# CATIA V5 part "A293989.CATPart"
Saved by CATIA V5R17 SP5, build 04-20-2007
Part number: 06F5001A1508PN-158
Revision: B
Definition: A293989
Nomenclature: BACKSHELL, 45 DEG, SHRINK BOOT ACCOM, SELF-SEATING
Source: bought
Description: BACKSHELL, 45 DEG, SHRINK BOOT ACCOM, SELF-SEATING
Publications: "Logical Termination.1", "BCP", "BCP_generated(BCP)", "Face_generated(BCP)", "BaCP", "Face_generated(BaCP)", "Line.1_generated(BaCP)"
Material "Density=.2850": density 7888.77 kg/m3
Bounding box of the stored display mesh (mm): x -7.112 to 45.125, y -15.845 to 15.845, z -26.761 to 15.845
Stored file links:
  C:\Users\u305772\OneDrive - Gulfstream Aerospace\AD PAG\Harness\A293989.CATPart
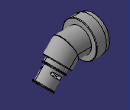
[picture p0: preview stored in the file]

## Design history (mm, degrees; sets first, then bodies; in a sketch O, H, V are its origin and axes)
Parameters
  PartNumber = "06F5001A1508PN-158"
  OtherKeywords = "BACKSHELL, 45 DEG, SHRINK BOOT ACCOM, SELF-SEATING"
  Comments = "0.866 x .039 in THREAD, ELECTROLESS NICKEL OVER STAINLESS STEEL."
  CAGECode = "07418"
  WeightComment = "SPEC"
  WeightSource = "SPEC"
  Volume = 8.93738e-06 (volume) {= smartVolume(Body1)}
  Density = 7916.45 (density)
  Weight = 0.155982 {= Volume *Density *2.20462262185}
  ExtraLength = 48.0568 mm {= C +D}
Set1
  Point1 "BCP": type Center, Curve edge [face of Shaft2 from Sketch7.L11 | face of Fillet1]
  Point2 "BaCP": type Center, Curve edge [face of Rib1 | face of Groove1 from Sketch4.L1]
  Point3: type Center, Curve edge [face of Groove1 from Sketch4.L2 | face of Slot1]
  Point4: (0, 0, 3.175), relative to Point2
  Line1: type PtPt, FirstPoint Point2, SecondPoint Point3
Body1 "PartBody" (main body)
  Sketch1 on zx-plane, origin (0, 0, 0), H (-1, 0, 0), V (0, 0, 1)
    point P1 (0, 0)
    line L1 (0, 0) -> (-18.3642, 0)
    line L2 (-18.3642, 0) -> (-26.2489, -7.8847)
    point P2 (-26.2489, -7.8847)
    point P3 (-18.3642, 0)
    point P4 (-39.36, -20.9958)
    angle L2 L1 = 45
    length L1 = 18.3642
    distance P3 P4 = 29.6926 {= D}
    distance P4 P2 = 18.542
    coincidence: P1 H, P1 V, P4 L2
    horizontal: L1 H
  Sketch2 on yz-plane, origin (0, 0, 0), H (0, 1, 0), V (0, 0, 1)
    circle A1 centre (0, 0) radius 10.9982
    construction line L1 (-10.9982, 0) -> (10.9982, 0)
    point P1 (-10.9982, 0)
    point P2 (10.9982, 0)
    length L1 = 21.9964
    coincidence: P1 A1, P1 H, A1 P2
    horizontal: L1 H
  Rib1: profile Sketch2, centre curve Sketch1
  Sketch3 on zx-plane, origin (0, 0, 0), H (-1, 0, 0), V (0, 0, 1)
    point P1 (-5.588, 11.0236)
    line L1 (-5.588, 11.0236) -> (-5.588, 15.9766)
    point P2 (-5.588, 15.9766)
    line L2 (-5.588, 15.9766) -> (3.4237, 15.9766)
    point P3 (3.4237, 15.9766)
    line L3 (3.4237, 15.9766) -> (3.937, 15.0876)
    point P4 (3.937, 15.0876)
    line L4 (3.937, 15.0876) -> (7.112, 15.0876)
    point P5 (7.112, 15.0876)
    line L5 (7.112, 15.0876) -> (7.112, 11.0236)
    point P6 (7.112, 11.0236)
    line L6 (7.112, 11.0236) -> (-5.588, 11.0236)
    axis line L7 (0, 0) -> (-5.588, 0)
    point P7 (-5.588, 0)
    point P8 (-5.588, -15.9766)
    point P9 (-5.588, -11.0236)
    construction line L8 (-5.588, -11.0236) -> (-5.588, -15.9766)
    point P10 (3.4237, -15.9766)
    construction line L9 (-5.588, -15.9766) -> (3.4237, -15.9766)
    point P11 (3.937, -15.0876)
    construction line L10 (3.4237, -15.9766) -> (3.937, -15.0876)
    point P12 (7.112, -15.0876)
    construction line L11 (3.937, -15.0876) -> (7.112, -15.0876)
    point P13 (7.112, -11.0236)
    construction line L12 (7.112, -15.0876) -> (7.112, -11.0236)
    construction line L13 (7.112, -11.0236) -> (-5.588, -11.0236)
    distance L5 L1 = 12.7
    length L4 = 3.175
    angle L4 L3 = 60
    distance L5 V = 7.112
    distance L6 L13 = 22.0472 {= `A THD` +.002 in}
    distance P5 P12 = 30.1752
    distance L4 L2 = 0.889
    vertical: L1 V, L5 V
    horizontal: L2 H, L4 H, L6 H, L7 H
    coincidence: P7 L1
    symmetry: P2 P8 L7, P1 P9 L7, L1 L8 L7, P3 P10 L7, L2 L9 L7, P4 P11 L7, L3 L10 L7, P5 P12 L7, L4 L11 L7, P6 P13 L7, L5 L12 L7, L6 L13 L7
  Shaft1: profile Sketch3, axis Sketch3.L7, angle 360
  Sketch4 on zx-plane, origin (0, 0, 0), H (-1, 0, 0), V (0, 0, 1)
    point P1 (0, 10.3632)
    line L1 (0, 10.3632) -> (-7.112, 10.3632)
    point P2 (-7.112, 10.3632)
    line L2 (-7.112, 10.3632) -> (-8.001, 9.4742)
    point P3 (-8.001, 9.4742)
    line L3 (-8.001, 9.4742) -> (-8.001, 0)
    point P4 (-8.001, 0)
    axis line L4 (-8.001, 0) -> (0, 0)
    line L5 (0, 0) -> (0, 10.3632)
    line L6 (0, 0) -> (-8.001, 0)
    point P5 (0, 0)
    point P6 (-8.001, 0)
    point P7 (-8.001, 0)
    point P8 (-8.001, -9.4742)
    construction line L7 (-8.001, -9.4742) -> (-8.001, 0)
    point P9 (-7.112, -10.3632)
    construction line L8 (-7.112, -10.3632) -> (-8.001, -9.4742)
    point P10 (0, -10.3632)
    construction line L9 (0, -10.3632) -> (-7.112, -10.3632)
    point P11 (0, 0)
    construction line L10 (0, 0) -> (0, -10.3632)
    construction line L11 (0, 0) -> (-8.001, 0)
    angle L1 L2 = 45
    length L1 = 7.112
    length L6 = 8.001
    distance L1 L9 = 20.7264 {= `A THD` -.05in}
    distance P8 P3 = 18.9484 (reference)
    coincidence: P1 V, P4 H, O L5, P4 L3, L6 L11
    horizontal: L1 H, L4 H, L6 H
    vertical: L3 V, L5 V
    symmetry: P6 P7 L4, P3 P8 L4, L3 L7 L4, P2 P9 L4, L2 L8 L4, P1 P10 L4, L1 L9 L4, P5 P11 L4, L5 L10 L4, L6 L11 L4
  Groove1: profile Sketch4, axis Sketch4.L4, angle 360
  Sketch5 on face of Groove1 from Sketch4.L3, origin (8.001, 0, 0), H (0, -1, 0), V (0, 0, 1)
    circle A1 centre (0, 0) radius 9.4742
    reference projected circle E1 centre (0, 0) radius 9.4742 from edge [face of Groove1 from Sketch4.L3 | face of Groove1 from Sketch4.L2]
    tangency: E1 A1
  Sketch6 on zx-plane, origin (0, 0, 0), H (-1, 0, 0), V (0, 0, 1)
    point P1 (-8.001, 0)
    line L1 (-8.001, 0) -> (-18.3642, 0)
    line L2 (-18.3642, 0) -> (-26.2489, -7.8847)
    point P3 (-26.2489, -7.8847)
    reference projected line E1 through (-9.1821, 9.1821) direction (-0.7071, -0.7071) from axis of face of Rib1
    reference projected line E2 (-20.5969, -13.5366) -> (-29.0814, -5.0521) from edge [face of Rib1 | face of Rib1]
    reference intersected line E3 (-8.001, -4.4755) -> (-8.001, 4.4755) from face of Groove1 from Sketch4.L3
    coincidence: P1 H, L2 E1, P3 E2, P1 E3
    horizontal: L1 H
  Slot1: profile Sketch5, centre curve Sketch6
  Sketch7 on zx-plane, origin (0, 0, 0), H (-1, 0, 0), V (0, 0, 1)
    axis line L1 (-18.3642, 0) -> (-39.36, -20.9958)
    point P1 (-18.3642, 0)
    point P2 (-39.36, -20.9958)
    point P3 (-34.8699, -25.486)
    line L2 (-34.8699, -25.486) -> (-20.8607, -11.4768)
    point P4 (-20.8607, -11.4768)
    line L3 (-20.8607, -11.4768) -> (-18.6516, -13.6859)
    line L4 (-20.2186, -13.9149) -> (-22.6433, -16.3396)
    line L5 (-22.6433, -16.3396) -> (-21.9653, -17.0176)
    point P5 (-21.9653, -17.0176)
    line L6 (-21.9653, -17.0176) -> (-22.8633, -17.9156)
    point P6 (-22.8633, -17.9156)
    line L7 (-22.8633, -17.9156) -> (-24.2193, -16.5596)
    point P7 (-24.2193, -16.5596)
    line L8 (-24.2193, -16.5596) -> (-33.1098, -25.45)
    point P8 (-33.1098, -25.45)
    line L9 (-33.1098, -25.45) -> (-32.4318, -26.1281)
    point P9 (-32.4318, -26.1281)
    line L10 (-32.4318, -26.1281) -> (-33.3298, -27.0261)
    point P10 (-33.3298, -27.0261)
    line L11 (-33.3298, -27.0261) -> (-34.8699, -25.486)
    point P11 (-29.841, -2.4965)
    point P13 (-35.3818, -3.6011)
    point P14 (-36.2798, -4.4991)
    point P15 (-34.9238, -5.8551)
    construction line L12 (-29.841, -2.4965) -> (-31.3811, -0.9564)
    construction line L13 (-31.3811, -0.9564) -> (-34.7038, -4.2791)
    construction line L14 (-34.7038, -4.2791) -> (-35.3818, -3.6011)
    construction line L15 (-35.3818, -3.6011) -> (-36.2798, -4.4991)
    construction line L16 (-36.2798, -4.4991) -> (-34.9238, -5.8551)
    point P16 (-43.8502, -16.5057)
    construction line L17 (-43.8502, -16.5057) -> (-29.841, -2.4965)
    point P17 (-43.8142, -14.7456)
    construction line L18 (-34.9238, -5.8551) -> (-43.8142, -14.7456)
    point P18 (-44.4923, -14.0676)
    construction line L19 (-43.8142, -14.7456) -> (-44.4923, -14.0676)
    point P19 (-45.3903, -14.9656)
    construction line L20 (-44.4923, -14.0676) -> (-45.3903, -14.9656)
    construction line L21 (-45.3903, -14.9656) -> (-43.8502, -16.5057)
    reference projected line E1 through (-9.1821, 9.1821) direction (-0.7071, -0.7071) from axis of face of Rib1
    reference projected line E2 (-20.5969, -13.5366) -> (-29.0814, -5.0521) from edge [face of Rib1 | face of Rib1]
    reference projected line E3 (-20.5969, -13.5366) -> (-29.0814, -5.0521) from edge [face of Rib1 | face of Rib1]
    line L22 (-20.2186, -13.9149) -> (-19.5496, -14.5839)
    point P23 (-19.5496, -14.5839)
    line L23 (-19.5496, -14.5839) -> (-18.6516, -13.6859)
    point P24 (-18.6516, -13.6859)
    point P25 (-32.0501, -0.2874)
    point P26 (-32.9481, -1.1854)
    construction line L24 (-32.9481, -1.1854) -> (-32.0501, -0.2874)
    reference intersected line E4 (-20.5969, -13.5366) -> (-29.0814, -5.0521) from face of Rib1
    length L1 = 29.6926
    length L10 = 1.27
    length L6 = 1.27
    distance L2 L17 = 12.7
    distance L8 L18 = 15.1384
    distance L6 L15 = 18.9738
    distance E2 L5 = 3.429
    distance L3 E3 = 1.27
    distance L24 L23 = 18.9484 {= Sketch4.distance(P8 P3)}
    coincidence: H P1, L11 P2, E1 L1, L22 E4
    perpendicularity: L3 L2, L8 L7
    parallelism: L4 L2, L7 L5, L9 L7, L10 L6, L11 L7, L22 L12, L23 L6
    symmetry: P4 P11 L1, P5 P13 L1, P6 P14 L1, P7 P15 L1, L3 L12 L1, L4 L13 L1, L5 L14 L1, L6 L15 L1, L7 L16 L1, P3 P16 L1, L2 L17 L1, P8 P17 L1, L8 L18 L1, P9 P18 L1, L9 L19 L1, P10 P19 L1, L10 L20 L1, L11 L21 L1, L18 L15 L20, P24 P25 L1, P23 P26 L1, L23 L24 L1, L6 L8 L4
  Shaft2: profile Sketch7, axis Sketch7.L1, angle 360
  Sketch8 on zx-plane, origin (0, 0, 0), H (-1, 0, 0), V (0, 0, 1)
    arc A1 centre (-35.4985, -9.9501) radius 1.27 from (-34.6005, -9.0521) to (-36.3966, -10.8481) ccw
    arc A2 centre (-28.3143, -17.1343) radius 1.27 from (-29.2123, -18.0324) to (-27.4163, -16.2363) ccw
    construction line L1 (-28.3143, -17.1343) -> (-35.4985, -9.9501)
    reference projected line E1 (-24.8212, -15.9577) -> (-31.5025, -9.2764) from edge [face of Shaft2 from Sketch7.L6 | face of Shaft2 from Sketch7.L7]
    line L2 (-34.6005, -9.0521) -> (-27.4163, -16.2363)
    line L3 (-29.2123, -18.0324) -> (-36.3966, -10.8481)
    reference projected line E2 (-24.8212, -15.9577) -> (-31.5025, -9.2764) from edge [face of Shaft2 from Sketch7.L6 | face of Shaft2 from Sketch7.L7]
    construction line L4 (-32.8045, -14.4403) -> (-31.0084, -12.6442)
    point P7 (-32.8045, -14.4403)
    point P8 (-31.0084, -12.6442)
    reference projected line E3 through (-9.1821, 9.1821) direction (-0.7071, -0.7071) from axis of face of Shaft2 from Sketch7.L8
    distance L2 E2 = 2.032
    distance L2 L3 = 2.54
    distance A2 A1 = 12.7 {= `X DIA`}
    parallelism: E1 L1, L2 L1, L3 L1
    tangency: L2 A2, L2 A1, A1 L3, L3 A2
    midpoint: P7 L3, P8 L2
    perpendicularity: L4 L2
    coincidence: L4 E3
  Pocket1: profile Sketch8, direction (0, -1, 0), through (limit type 6), opposite side through (limit type 6)
  Fillet1: radius 0.508, on edge [face of Rib1 | face of Rib1]; edge [face of Shaft1 from Sketch3.L2 | face of Shaft1 from Sketch3.L1]; edge [face of Shaft2 from Sketch7.L5 | face of Shaft2 from Sketch7.L6]; edge [face of Shaft2 from Sketch7.L6 | face of Shaft2 from Sketch7.L7]; edge [face of Shaft2 from Sketch7.L9 | face of Shaft2 from Sketch7.L10]; edge [face of Shaft2 from Sketch7.L10 | face of Shaft2 from Sketch7.L11]; edge [face of Shaft2 from Sketch7.L11 | face of Shaft2 from Sketch7.L2]; edge [face of Rib1 | face of Shaft2]; edge [face of Shaft2 from Sketch7.L2 | face of Shaft2 from Sketch7.L3]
